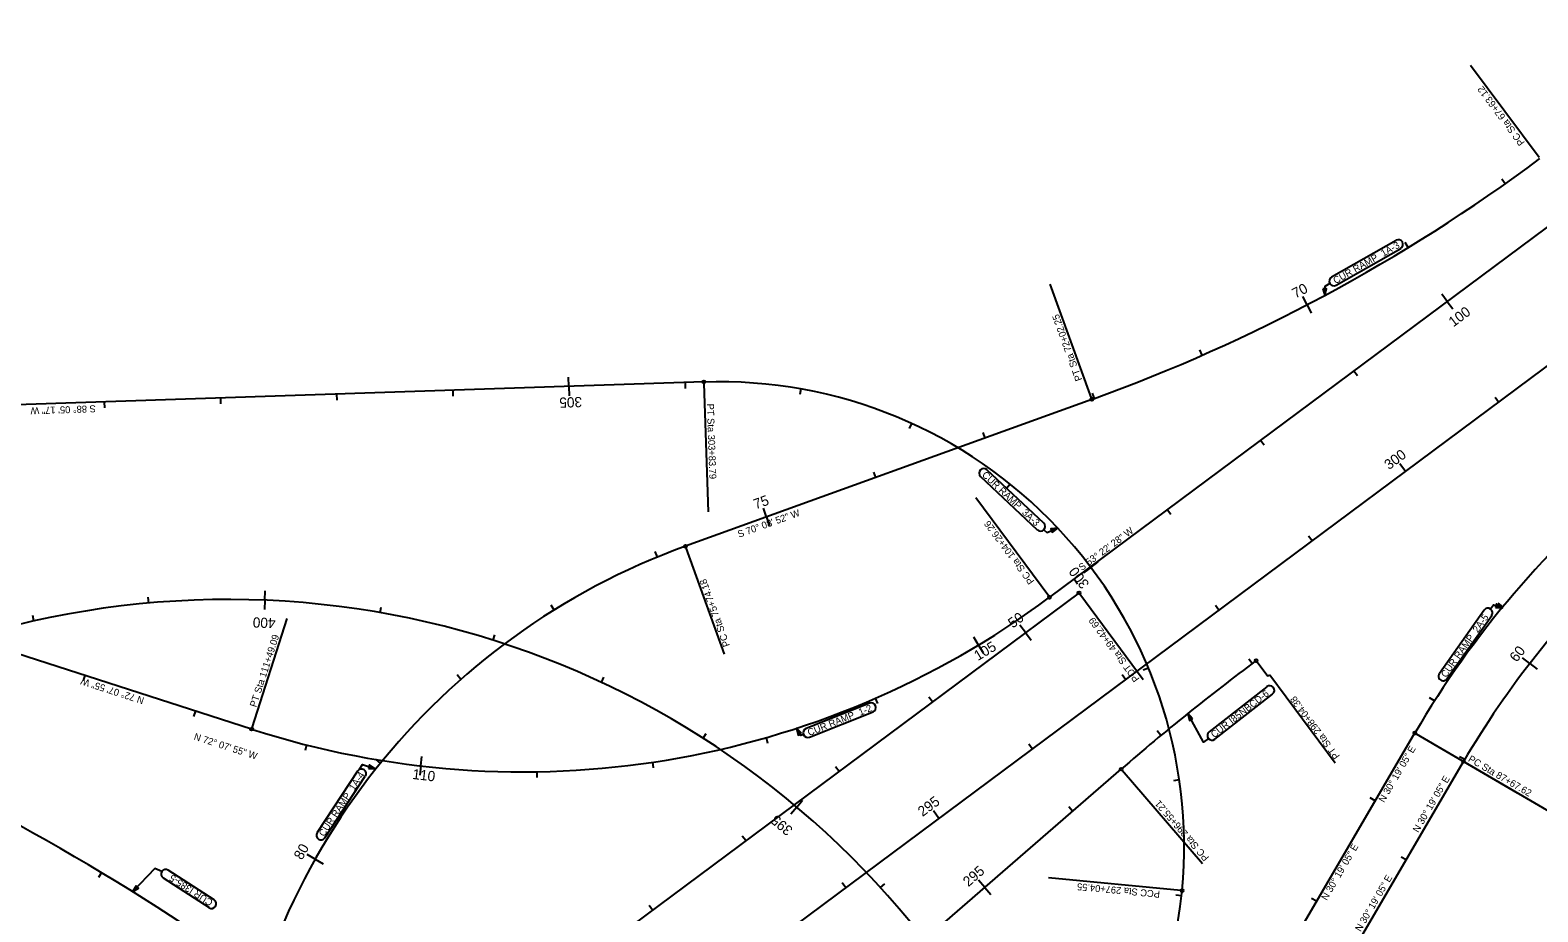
# Model space of a CAD drawing. Extents: x 1603540 to 1622629, y 1083934 to 1103503.
# Drawn here: x 1610388 to 1611685, y 1094104 to 1094862 of the extents above; entities that cross this region are included whole.
import ezdxf

# ---------------------------------------------------------------- set-up
doc = ezdxf.new("R2010")
doc.units = 0
for name, color, linetype in [('RD_EX_BldgChurch', 7, 'Continuous'), ('RD_EX_Fence_ChLk', 7, 'Continuous'), ('RD_EX_H2O', 7, 'Continuous'), ('RD_EX_Misc', 7, 'Continuous'), ('RD_HC_CL', 7, 'Continuous'), ('RD_PG_GR', 7, 'Continuous')]:
    doc.layers.add(name, color=color, linetype=linetype)

msp = doc.modelspace()

# ---------------------------------------------------------------- linework, layer by layer
at = {"layer": 'RD_EX_BldgChurch'}
for p, q in [((1611686.4, 1094752.4), (1611627.5, 1094831.5)), ((1611301.2, 1094545.5), (1611265.8, 1094643.5)), ((1610967.7, 1094558), (1610971.4, 1094447.7)), ((1611264.5, 1094375.2), (1611201.8, 1094459.6)), ((1610952.2, 1094416.8), (1610985.3, 1094325.2)), ((1611291.3, 1094377), (1611345.8, 1094303.6)), ((1610579, 1094262), (1610609.3, 1094356)), ((1611443.7, 1094318.7), (1611453, 1094306.3)), ((1611453, 1094306.3), (1611454.6, 1094307.5)), ((1611454.6, 1094307.5), (1611510.9, 1094231.7)), ((1611580.6, 1094256.8), (1611667.6, 1094206)), ((1611622.5, 1094232.4), (1611772.2, 1094144.8)), ((1611327.5, 1094225.4), (1611396.8, 1094145.4)), ((1611378, 1094122.1), (1611264.2, 1094132.8))]:
    msp.add_line(p, q, dxfattribs=at)
for centre in [(1610967.7, 1094559.3), (1611301.6, 1094544.3), (1610951.8, 1094418), (1611265.2, 1094374.2), (1611290.5, 1094378), (1611443, 1094319.7), (1610578.6, 1094260.8), (1611579.5, 1094257.5), (1611326.7, 1094226.4), (1611621.4, 1094233), (1611379.3, 1094122)]:
    msp.add_circle(centre, 1.25, dxfattribs=at)
at = {"layer": 'RD_EX_H2O'}
for p, q in [((1611657.3, 1094729.7), (1611654.4, 1094733.8)), ((1611573.7, 1094674.8), (1611571.1, 1094679.1)), ((1611486.7, 1094625.6), (1611483, 1094632.7)), ((1611607.3, 1094628.5), (1611602.6, 1094634.9)), ((1611607.3, 1094628.5), (1611612.1, 1094622.1)), ((1611486.7, 1094625.6), (1611490.4, 1094618.5)), ((1611396.6, 1094582.3), (1611394.5, 1094586.9)), ((1610851.5, 1094555.4), (1610851.3, 1094563.4)), ((1611527.1, 1094568.8), (1611530.1, 1094564.8)), ((1610751.6, 1094552.1), (1610751.7, 1094547.1)), ((1610851.5, 1094555.4), (1610851.8, 1094547.4)), ((1610951.5, 1094558.7), (1610951.6, 1094553.7)), ((1611051.1, 1094553.3), (1611050.2, 1094548.4)), ((1610451.7, 1094542), (1610451.9, 1094537)), ((1610551.7, 1094545.4), (1610551.9, 1094540.4)), ((1610651.6, 1094548.7), (1610651.8, 1094543.7)), ((1611303.8, 1094545.1), (1611302.1, 1094549.8)), ((1611651.5, 1094542), (1611648.6, 1094546.1)), ((1611146.3, 1094523.7), (1611144.3, 1094519.2)), ((1611209.7, 1094511.1), (1611208, 1094515.8)), ((1611446.8, 1094509.2), (1611449.8, 1094505.2)), ((1611571.3, 1094482.4), (1611566.5, 1094488.8)), ((1611115.6, 1094477.2), (1611113.9, 1094481.9)), ((1611231.3, 1094471.5), (1611228.2, 1094467.6)), ((1611021.6, 1094443.2), (1611018.9, 1094450.7)), ((1611366.6, 1094449.5), (1611369.5, 1094445.5)), ((1611021.6, 1094443.2), (1611024.3, 1094435.7)), ((1611491, 1094422.7), (1611488, 1094426.7)), ((1610927.7, 1094408.7), (1610925.8, 1094413.4)), ((1611300.7, 1094399.9), (1611294.3, 1094395.1)), ((1611300.7, 1094399.9), (1611307.1, 1094404.7)), ((1611286.3, 1094389.9), (1611289.3, 1094385.8)), ((1610490, 1094369.2), (1610489.6, 1094374.2)), ((1610589.9, 1094371.6), (1610589.6, 1094363.6)), ((1610589.9, 1094371.6), (1610590.3, 1094379.6)), ((1611655.2, 1094365.9), (1611651.3, 1094369.1)), ((1610391.3, 1094353.7), (1610390.2, 1094358.6)), ((1610689.3, 1094360.9), (1610690.1, 1094365.8)), ((1610838.8, 1094363.2), (1610836.2, 1094367.5)), ((1611410.8, 1094363.1), (1611407.8, 1094367.1)), ((1611244.5, 1094343.8), (1611239.7, 1094350.3)), ((1611244.5, 1094343.8), (1611249.3, 1094337.4)), ((1610786.4, 1094337.2), (1610787.9, 1094342)), ((1611204, 1094333.1), (1611199.9, 1094340)), ((1611204, 1094333.1), (1611208.1, 1094326.3)), ((1611439.5, 1094317.1), (1611436.5, 1094321.1)), ((1611678.4, 1094317.3), (1611672.1, 1094322.2)), ((1611678.4, 1094317.3), (1611684.7, 1094312.4)), ((1610435, 1094307.1), (1610433.5, 1094302.3)), ((1610758.7, 1094303.6), (1610755.3, 1094307.4)), ((1610879.5, 1094301), (1610881.6, 1094305.5)), ((1611330.5, 1094303.4), (1611327.5, 1094307.4)), ((1611350.3, 1094313.3), (1611345.6, 1094311.4)), ((1611115.2, 1094287.3), (1611117.2, 1094282.7)), ((1611164.3, 1094284.2), (1611161.3, 1094288.2)), ((1611596.4, 1094285.1), (1611592.2, 1094287.8)), ((1610530.2, 1094276.4), (1610528.7, 1094271.6)), ((1610967.1, 1094252.9), (1610969.8, 1094257.1)), ((1611021.2, 1094253.5), (1611022.5, 1094248.7)), ((1611360.9, 1094255.3), (1611357.7, 1094259.2)), ((1610625.8, 1094247.2), (1610624.6, 1094242.4)), ((1611250.3, 1094243.8), (1611247.3, 1094247.8)), ((1610689.5, 1094231.5), (1610685.6, 1094234.7)), ((1610724.1, 1094229.2), (1610723.2, 1094221.3)), ((1610724.1, 1094229.2), (1610725, 1094237.2)), ((1610923.5, 1094232.4), (1610924.2, 1094227.4)), ((1611084, 1094224.5), (1611081, 1094228.5)), ((1611622.4, 1094234.6), (1611618, 1094237.1)), ((1610823.9, 1094224.2), (1610824, 1094219.2)), ((1611376.8, 1094217.2), (1611371.9, 1094216.4)), ((1611545.4, 1094199.1), (1611541.1, 1094201.6)), ((1611047.6, 1094193.7), (1611042.4, 1094187.6)), ((1611047.6, 1094193.7), (1611052.7, 1094199.8)), ((1611170, 1094184.1), (1611165.2, 1094190.5)), ((1611285, 1094190.2), (1611281.7, 1094194)), ((1611003.8, 1094164.9), (1611000.8, 1094168.9)), ((1610633.3, 1094149), (1610626.3, 1094152.9)), ((1610633.3, 1094149), (1610640.2, 1094145.1)), ((1611571.9, 1094148.3), (1611567.6, 1094150.8)), ((1610449.3, 1094137.4), (1610446.7, 1094133.2)), ((1611089.8, 1094124.4), (1611086.8, 1094128.5)), ((1611119.6, 1094124.5), (1611123.3, 1094127.8)), ((1611209.4, 1094124.7), (1611204.1, 1094130.8)), ((1611209.4, 1094124.7), (1611214.6, 1094118.7)), ((1610923.5, 1094105.2), (1610920.5, 1094109.2)), ((1611378.8, 1094117.4), (1611373.8, 1094118)), ((1611494.9, 1094112.8), (1611490.6, 1094115.3))]:
    msp.add_line(p, q, dxfattribs=at)
at = {"layer": 'RD_HC_CL'}
for p, q in [((1614436.6, 1096731.7), (1611265.2, 1094374.2)), ((1609261, 1092765), (1614429, 1096606.7)), ((1610967.7, 1094559.3), (1609851.2, 1094522)), ((1611301.6, 1094544.3), (1610951.8, 1094418)), ((1611290.5, 1094378), (1610191.6, 1093561.1)), ((1610578.6, 1094260.8), (1610318, 1094344.8)), ((1611450.7, 1094037.2), (1611579.5, 1094257.5)), ((1611016, 1093957.2), (1611326.7, 1094226.4)), ((1611524, 1094066.3), (1611621.4, 1094233))]:
    msp.add_line(p, q, dxfattribs=at)
for centre, radius, start, end in [((1610792.2, 1095955.2), 1500, 289.8521, 306.6256), ((1610981, 1094159.5), 400, 354.6184, 91.912), ((1612294.7, 1093839.2), 828.5, 129.2926, 149.6819), ((1611155.6, 1093853.7), 600, 109.8521, 236.724), ((1609417.4, 1092424.2), 2000, 56.1301, 81.5065), ((1612294.7, 1093839.2), 780, 133.359, 149.6819), ((1610558.2, 1093612.3), 760, 18.4471, 165.9491), ((1610811.8, 1094984.1), 760, 252.1319, 306.6256), ((1612636.2, 1092714.6), 2000, 126.6256, 130.899), ((1611020.8, 1094155.7), 360, 286.7519, 354.6184)]:
    msp.add_arc(centre, radius, start, end, dxfattribs=at)
at = {"layer": 'RD_PG_GR'}
for p, q in [((1611563.3, 1094681.1), (1611507.8, 1094649.4)), ((1611511.8, 1094642.5), (1611567.3, 1094674.2)), ((1611205.8, 1094478), (1611254.6, 1094432.1)), ((1611260.1, 1094437.9), (1611211.3, 1094483.9)), ((1611639.1, 1094363.1), (1611600.6, 1094308.7)), ((1611607.1, 1094304.1), (1611645.6, 1094358.5)), ((1611452.1, 1094297.3), (1611402.5, 1094258.5)), ((1611407.4, 1094252.2), (1611457, 1094291)), ((1611110.4, 1094283.1), (1611055.7, 1094261.3)), ((1611058.7, 1094253.9), (1611113.3, 1094275.7)), ((1610669.7, 1094224.6), (1610635, 1094171.8)), ((1610641.7, 1094167.4), (1610676.4, 1094220.3)), ((1610546.4, 1094114), (1610506.9, 1094139.6)), ((1610502.5, 1094132.9), (1610542.1, 1094107.3))]:
    msp.add_line(p, q, dxfattribs=at)
for points in [[(1611506.3, 1094644), (1611502, 1094641.5), (1611502, 1094633.7)], [(1611260.3, 1094432.2), (1611262.9, 1094429.8), (1611272.3, 1094433.6)], [(1611644.6, 1094364.1), (1611647.2, 1094367.7), (1611654.8, 1094365.2)], [(1611401.8, 1094252.8), (1611397.7, 1094249.6), (1611384, 1094274.1)], [(1611053.5, 1094256.1), (1611051.1, 1094255.2), (1611047.3, 1094261.5)], [(1610671.4, 1094226.4), (1610674, 1094230.3), (1610685.1, 1094226.8)], [(1610501.3, 1094138.4), (1610495.3, 1094141.1), (1610476.2, 1094121)]]:
    msp.add_lwpolyline(points, dxfattribs=at)
for points in [[(1611500.4, 1094639.5), (1611502, 1094633.7), (1611503.5, 1094639.5)], [(1611267.5, 1094430), (1611272.3, 1094433.6), (1611266.3, 1094432.9)], [(1611648.8, 1094365.5), (1611654.8, 1094365.2), (1611649.7, 1094368.5)], [(1611388.2, 1094269.8), (1611384, 1094274.1), (1611385.5, 1094268.3)], [(1611051.6, 1094257.3), (1611047.3, 1094261.5), (1611048.9, 1094255.7)], [(1610679.1, 1094227), (1610685.1, 1094226.8), (1610680.1, 1094230)], [(1610479.1, 1094126.2), (1610476.2, 1094121), (1610481.3, 1094124.1)]]:
    msp.add_lwpolyline(points, close=True, dxfattribs=at)
for centre, start, end in [((1611565.3, 1094677.7), 299.726, 119.726), ((1611509.8, 1094646), 119.726, 299.726), ((1611208.6, 1094480.9), 46.726, 226.726), ((1611257.4, 1094435), 226.726, 46.726), ((1611642.3, 1094360.8), 324.726, 144.726), ((1611603.8, 1094306.4), 144.726, 324.726), ((1611454.6, 1094294.2), 308.0494, 128.0494), ((1611111.8, 1094279.4), 291.726, 111.726), ((1611057.2, 1094257.6), 111.726, 291.726), ((1611404.9, 1094255.3), 128.0494, 308.0494), ((1610673.1, 1094222.5), 326.7025, 146.7025), ((1610638.3, 1094169.6), 146.7025, 326.7025), ((1610504.7, 1094136.2), 57.0805, 237.0805), ((1610544.2, 1094110.6), 237.0805, 57.0805)]:
    msp.add_arc(centre, 4, start, end, dxfattribs=at)

# ---------------------------------------------------------------- texts
at = {"layer": 'RD_EX_BldgChurch'}
for s, rotation, p in [('PC Sta 67+63.12', 126.6256, (1611674.3, 1094765.2)), ('PT Sta 72+02.25', 109.8521, (1611293.4, 1094561.3)), ('PT Sta 303+83.79', 271.912, (1610970.3, 1094540.6)), ('PC Sta 104+26.26', 126.6256, (1611252.4, 1094388)), ('PC Sta 75+74.18', 109.8521, (1610990.3, 1094332.8)), ('POT Sta 49+42.69', 126.6256, (1611342.9, 1094304.1)), ('PT Sta 111+49.09', 72.1319, (1610582.5, 1094279.2)), ('PT Sta 298+04.38', 126.6256, (1611515.2, 1094237.7)), ('PC Sta 87+67.62', 329.6819, (1611624.8, 1094233.5)), ('PC Sta 296+55.21', 130.899, (1611402.8, 1094150.5)), ('PCC Sta 297+04.55', 174.6184, (1611360.4, 1094121.7))]:
    msp.add_text(s, height=6, rotation=rotation, dxfattribs=at).set_placement(p)
at = {"layer": 'RD_EX_Fence_ChLk'}
for s, rotation, p in [('S 88%%d 05\' 17" W', 181.912, (1610444.4, 1094539.3)), ('S 70%%d 08\' 52" W', 19.8521, (1610998, 1094425.3)), ('S 53%%d 22\' 28" W', 36.6256, (1611292.9, 1094396.6)), ('N 72%%d 07\' 55" W', 162.1319, (1610486.6, 1094287.8)), ('N 72%%d 07\' 55" W', 342.1319, (1610528.4, 1094251.9)), ('N 30%%d 19\' 05" E', 59.6819, (1611553, 1094197.2)), ('N 30%%d 19\' 05" E', 59.6819, (1611582.4, 1094171.4)), ('N 30%%d 19\' 05" E', 59.6819, (1611503.7, 1094113)), ('N 30%%d 19\' 05" E', 59.6819, (1611532.8, 1094086.2))]:
    msp.add_text(s, height=6, rotation=rotation, dxfattribs=at).set_placement(p)
at = {"layer": 'RD_EX_Misc'}
for s, rotation, p in [('70', 27.5776, (1611476.7, 1094630.9)), ('100', 36.6256, (1611612.6, 1094606.2)), ('305', 181.912, (1610862.7, 1094546.5)), ('300', 36.6256, (1611557.2, 1094483.4)), ('75', 19.8521, (1611012.3, 1094449.7)), ('300', 126.938, (1611299.8, 1094385.7)), ('400', 177.6073, (1610599.3, 1094356.2)), ('50', 36.6256, (1611233.5, 1094347.2)), ('105', 31.0666, (1611203.5, 1094319.3)), ('60', 52.1988, (1611667.1, 1094317.8)), ('110', 353.372, (1610716.6, 1094218)), ('295', 36.6256, (1611155.9, 1094185.2)), ('395', 139.9127, (1611045, 1094175.1)), ('80', 60.5147, (1610621.9, 1094147.7)), ('295', 40.899, (1611195.3, 1094124.8))]:
    msp.add_text(s, height=8.75, rotation=rotation, dxfattribs=at).set_placement(p)
at = {"layer": 'RD_PG_GR'}
for s, rotation, p in [('CUR RAMP_1A-3', 29.726, (1611511.3, 1094643.4)), ('CUR RAMP_3A-3', 316.726, (1611206.5, 1094478.8)), ('CUR RAMP_2A-5', 54.726, (1611606.3, 1094304.6)), ('CUR I85NBCD-6', 38.0494, (1611406.8, 1094252.9)), ('CUR RAMP_1-2', 21.726, (1611058.3, 1094254.8)), ('CUR RAMP_1A-4', 56.7025, (1610640.9, 1094167.9)), ('CUR I385-5', 147.0805, (1610545.9, 1094113.2))]:
    msp.add_text(s, height=6, rotation=rotation, dxfattribs=at).set_placement(p)

doc.saveas('drawing.dxf')
